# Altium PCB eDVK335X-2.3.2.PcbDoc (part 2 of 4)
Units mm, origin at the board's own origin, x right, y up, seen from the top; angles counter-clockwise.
Board outline 100.04 x 80.07 mm, 4 copper layers (Top Layer, Layer 1, Layer 2, Bottom Layer), stack 0.569 mm thick; 245 components, 272 nets, 1313 pads, 662 vias.
Unrouted connection lines stored in the file: 1.
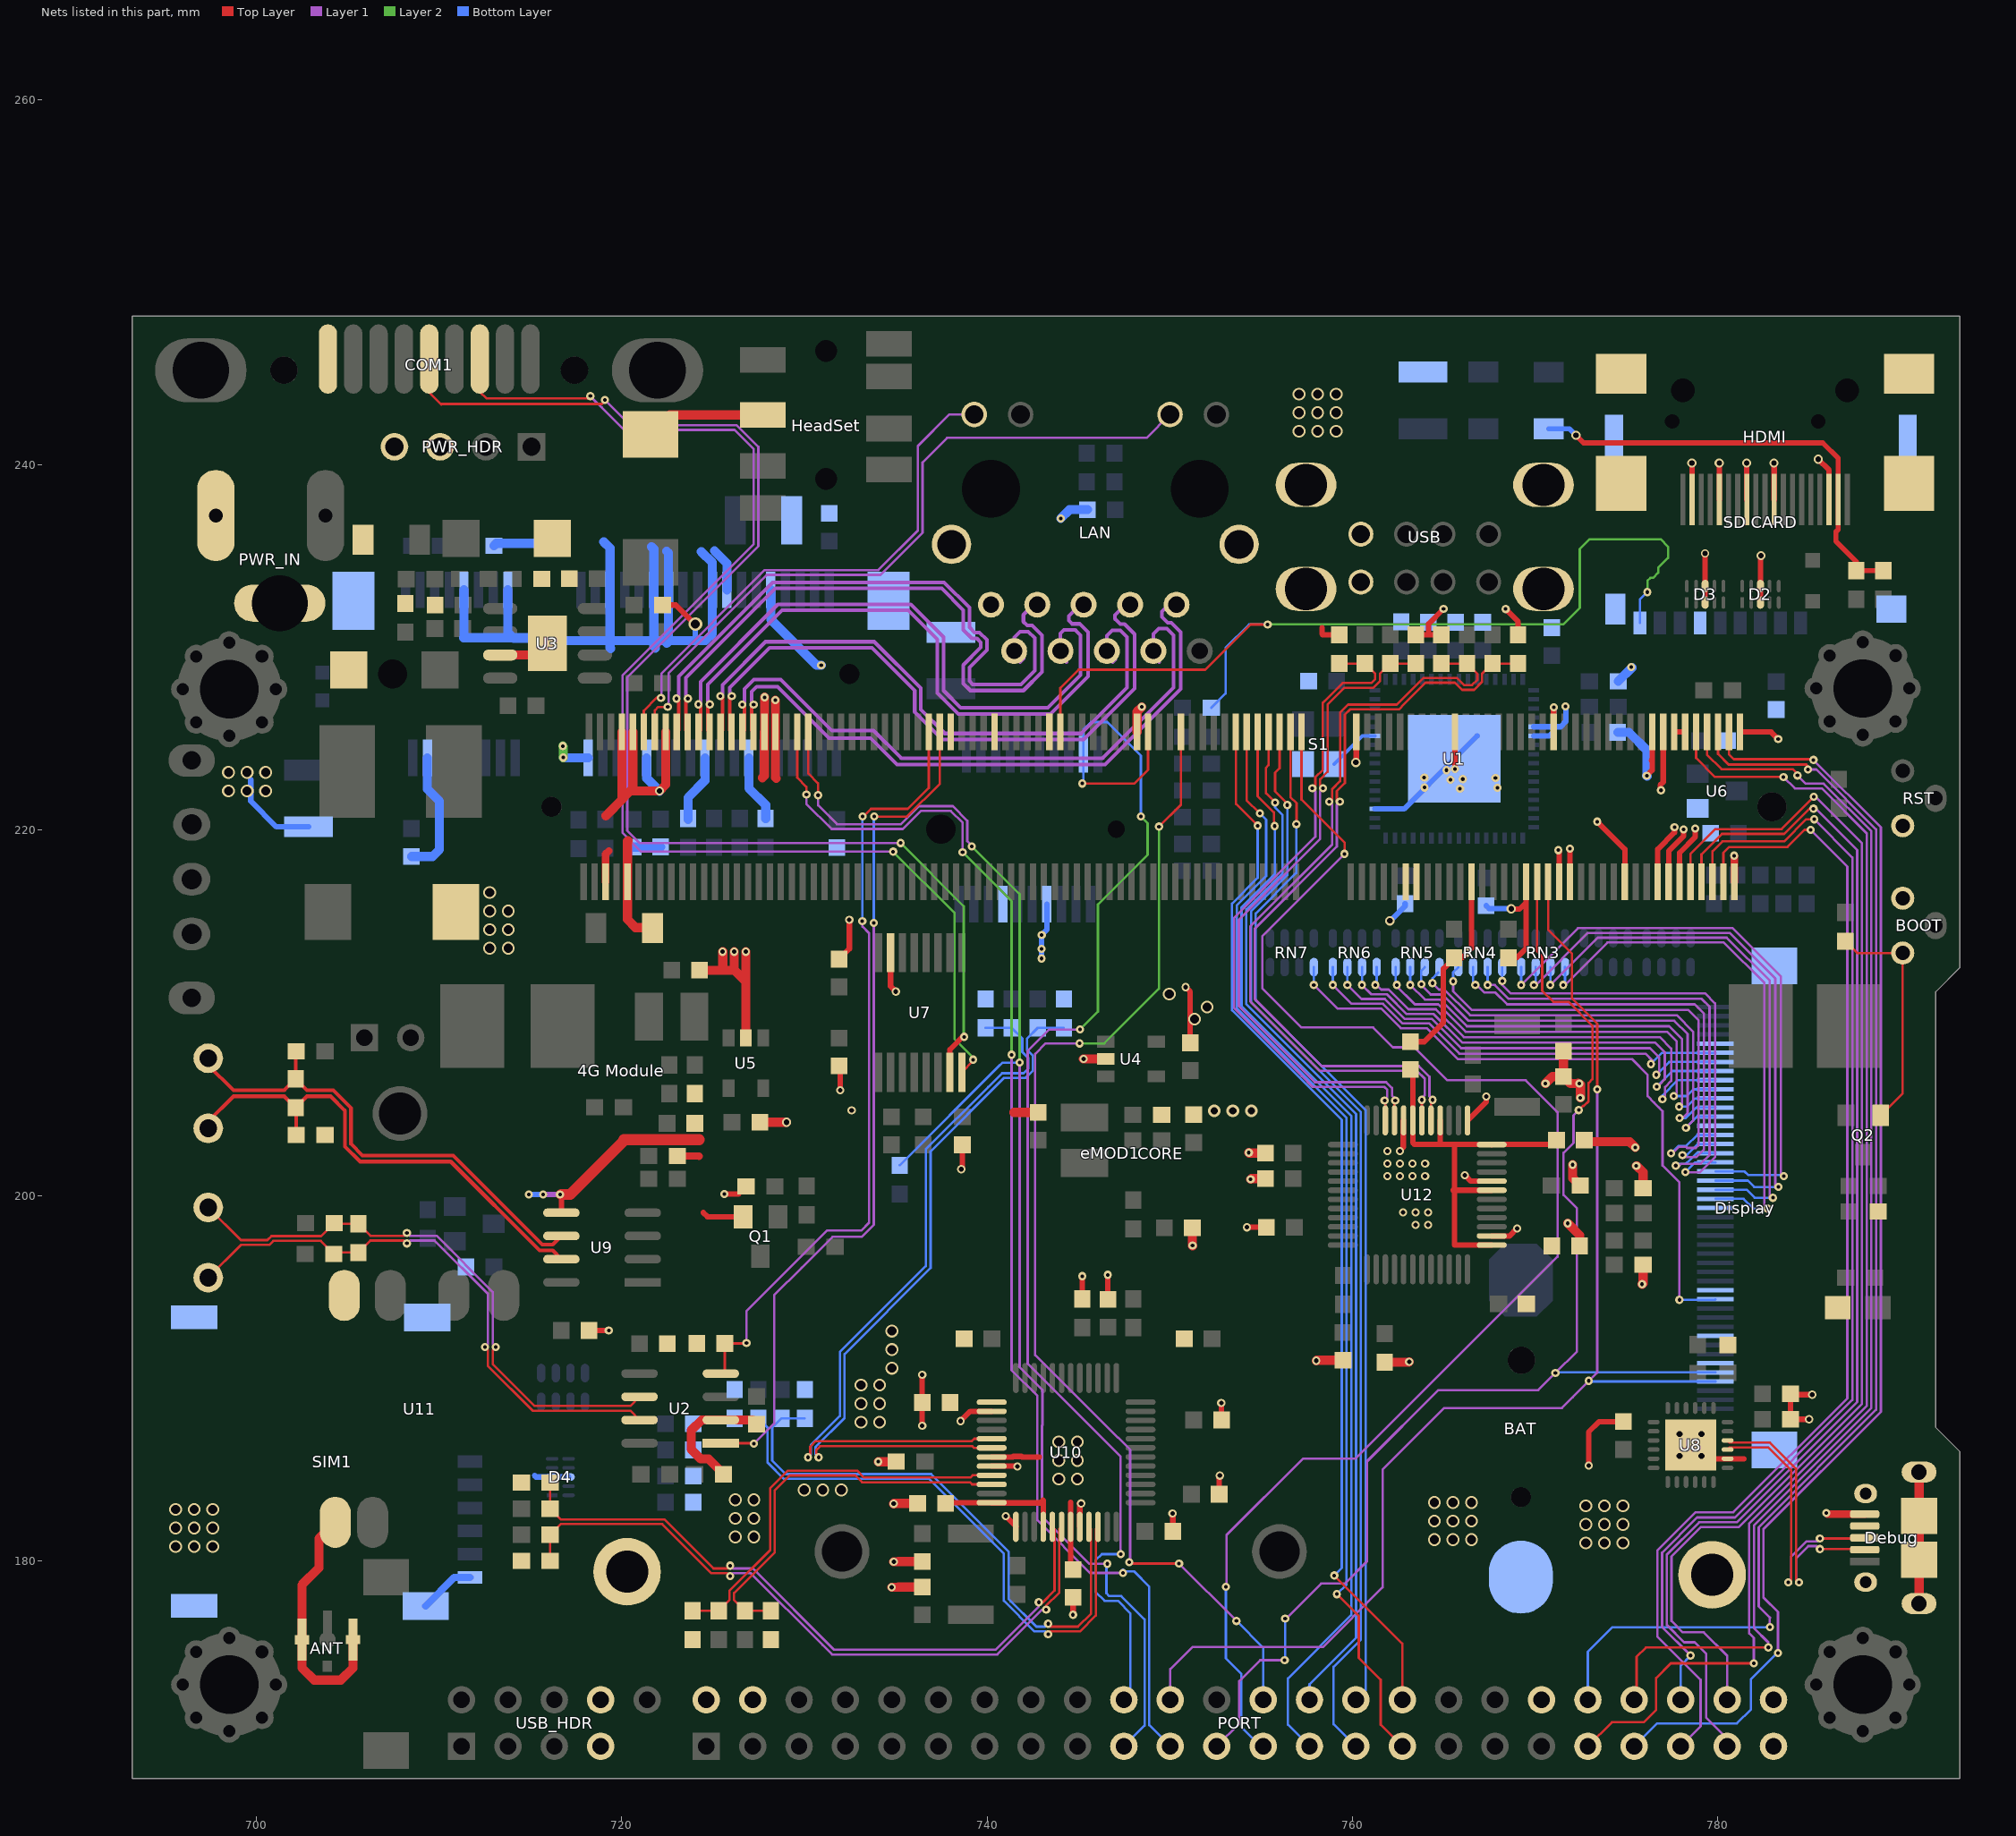
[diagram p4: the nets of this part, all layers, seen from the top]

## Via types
v1: diameter 0.45, hole 0.2, Top Layer to Bottom Layer, tented both sides, 424 vias
v2: diameter 0.7, hole 0.5, Top Layer to Bottom Layer, tented both sides, 146 vias
v3: diameter 0.45, hole 0.25, Top Layer to Bottom Layer, tented both sides, 55 vias
v4: diameter 0.5, hole 0.3, Top Layer to Bottom Layer, tented both sides, 17 vias
v5: diameter 0.7, hole 0.4, Top Layer to Bottom Layer, tented both sides, 13 vias
v6: diameter 0.66, hole 0.33, Top Layer to Bottom Layer, tented both sides, 4 vias
v7: diameter 0.75, hole 0.5, Top Layer to Bottom Layer, tented both sides, 1 vias
v8: diameter 0.5, hole 0.2, Top Layer to Bottom Layer, tented both sides, 1 vias
v9: diameter 0.45, hole 0.3, Top Layer to Bottom Layer, tented both sides, 1 vias

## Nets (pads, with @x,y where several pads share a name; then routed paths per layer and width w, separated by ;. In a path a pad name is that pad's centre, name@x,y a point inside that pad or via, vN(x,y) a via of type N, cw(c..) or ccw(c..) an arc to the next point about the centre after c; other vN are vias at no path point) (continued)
1D3_N: R94.2 R150.1 U12.17 | length 43
  Top Layer w0.13: v1(759.31,221.56) 759.19,221.56 759.15,221.6 759.15,222.142 759.59,222.582 759.59,226.34 759.87,226.62 762.54,226.62 762.84,226.92 ; 762.84,226.92 763.238,227.318 ; 763.238,227.318 764,228.08 765.612,228.08 766.002,227.69 766.658,227.69 767.095,228.127 767.095,228.559 R94.2@767.663,229.127 R150.1@769.06,229.127 ; U12.17@764.302,204.115 v1@764.302,205.168 ; v1@764.302,205.34 v1@764.302,205.24 ; v1(764.388,205.24) v1@764.302,205.24 ; v1@764.302,205.168 v1@764.302,205.24 ; v1@764.302,205.168 764.23,205.24 v1@764.302,205.24
  Layer 1 w0.13: v1(759.31,221.56) 759.15,221.4 759.15,219.11 754.66,214.62 754.66,210.75 758.32,207.09 763.638,207.09 764.22,206.508 764.22,205.422 v1@764.302,205.34
1D3_P: R95.2 R149.1 U12.18 | length 42.8
  Top Layer w0.13: v1(758.73,221.56) 758.85,221.56 758.89,221.6 758.89,222.25 759.33,222.69 759.33,226.448 759.762,226.88 762.432,226.88 762.732,227.18 ; 762.732,227.18 762.978,227.426 ; 762.978,227.426 763.892,228.34 765.72,228.34 766.11,227.95 766.55,227.95 766.835,228.235 766.835,228.559 R95.2@766.266,229.127 R149.1@764.869,229.127 ; U12.18@763.802,204.115 v1@763.802,205.246 ; v1@763.802,205.329 v1@763.802,205.246 ; v1(763.806,205.241) v1@763.802,205.246
  Layer 1 w0.13: v1(758.73,221.56) 758.89,221.4 758.89,219.218 754.4,214.728 754.4,210.642 757.702,207.34 758.212,206.83 763.53,206.83 763.96,206.4 763.96,205.488 v1@763.802,205.329
1D4_N: R51.2 R123.1 U12.21 | length 36.7
  Top Layer w0.13: v1(758.39,222.3) 758.38,222.3 758.23,222.45 758.23,222.792 758.64,223.202 758.64,226.87 759.57,227.8 761.144,227.8 761.507,228.162 761.507,228.559 R51.2@762.075,229.127 R123.1@763.472,229.127 ; U12.21@762.302,204.115 v1@762.302,205.34
  Layer 1 w0.13: v1(758.39,222.3) 758.23,222.14 758.23,219.54 753.78,215.09 753.78,210.37 757.94,206.21 761.85,206.21 762.17,205.89 762.17,205.471 v1@762.302,205.34
  other v1: 762.342,205.2
1D4_P: R52.2 R122.1 U12.22 | length 36.9
  Top Layer w0.13: v1(757.81,222.3) 757.82,222.3 757.97,222.45 757.97,222.9 758.38,223.31 758.38,226.978 758.456,227.054 759.462,228.06 761.037,228.06 761.247,228.27 761.247,228.559 R52.2@760.678,229.127 R122.1@759.281,229.127 ; v1@761.719,205.24 v1@761.802,205.24 ; U12.22@761.802,204.115 v1@761.802,205.24 ; v1@761.802,205.329 v1@761.802,205.24
  Layer 1 w0.13: v1(757.81,222.3) 757.97,222.14 757.97,219.648 753.52,215.198 753.52,210.262 757.232,206.55 757.832,205.95 761.742,205.95 761.91,205.782 761.91,205.351 v1(761.758,205.2)
2D1_N: R42.2 R125.1 U10.9 | length 22
  Top Layer w0.13: R125.1@723.882,177.271 R42.2@725.309,177.271 725.892,177.855 725.892,178.348 728.12,180.576 728.12,183.968 729.092,184.94 732.89,184.94 733.263,184.567 739.08,184.567 739.2,184.687 U10.9@740.251,184.687
2D1_P: R43.2 R124.1 U10.10 | length 21.6
  Top Layer w0.13: R124.1@728.162,177.271 R43.2@726.735,177.271 726.152,177.855 726.152,178.24 728.38,180.468 728.38,183.86 729.2,184.68 732.782,184.68 733.155,184.307 739.06,184.307 739.18,184.187 U10.10@740.251,184.187
2D2_N: R60.2 R119.1 U10.5 | length 41.7
  Top Layer w0.13: v1(730.195,185.67) 730.32,185.795 730.32,186.257 730.623,186.56 739.17,186.56 739.297,186.687 U10.5@740.251,186.687
  Bottom Layer w0.13: v1(730.195,185.67) 730.355,185.83 730.355,186.348 731.94,187.933 731.94,191.43 736.65,196.14 736.65,202.528 740.07,205.948 740.822,206.7 742,206.7 742.25,206.95 742.25,207.54 741.93,207.86 741.93,208.599 R60.2@741.347,209.183 R119.1@739.92,209.183
2D2_P: R61.2 R118.1 U10.6 | length 41.2
  Top Layer w0.13: v1(730.775,185.67) 730.65,185.795 730.65,186.07 730.86,186.28 739.19,186.28 739.283,186.187 U10.6@740.251,186.187
  Bottom Layer w0.13: v1(730.775,185.67) 730.615,185.83 730.615,186.24 732.2,187.825 732.2,191.322 736.91,196.032 736.91,202.42 740.93,206.44 742.108,206.44 742.51,206.842 742.51,207.648 742.19,207.968 742.19,208.599 R61.2@742.773,209.183 R118.1@744.2,209.183
2D3_N: R62.2 R152.1 U10.17 | length 37.6
  Top Layer w0.13: R152.1@716.081,184.283 R62.2@716.081,182.856 716.664,182.273 722.327,182.273 725.02,179.58 725.77,179.58 v1(725.93,179.74) ; v1(742.827,177.733) 742.85,177.71 743.03,177.71 743.696,178.375 743.696,181.742 U10.17@743.576,181.862
  Layer 1 w0.13: v1@725.95,179.58 725.93,179.6 v1(725.93,179.74) 726.09,179.58 727.18,179.58 731.63,175.13 740.45,175.13 742.827,177.507 v1(742.827,177.733)
2D3_P: R63.2 R151.1 U10.18 | length 38
  Top Layer w0.13: R151.1@716.081,180.021 R63.2@716.081,181.43 716.664,182.013 722.219,182.013 724.912,179.32 725.77,179.32 v1(725.93,179.16) ; v1(743.237,177.323) 743.214,177.346 743.214,177.526 743.955,178.268 743.955,181.742 U10.18@744.075,181.862
  Layer 1 w0.13: v1@725.95,179.32 725.93,179.3 v1(725.93,179.16) 726.09,179.32 727.072,179.32 730.997,175.395 731.522,174.87 740.558,174.87 743.011,177.323 v1(743.237,177.323)
2D4_N: R96.2 R148.1 U10.21 | length 31.8
  Top Layer w0.13: v1(743.34,176.56) 743.34,176.49 743.43,176.4 744.976,176.4 745.696,177.12 745.696,181.742 U10.21@745.576,181.862
  Bottom Layer w0.13: R148.1@730.02,187.803 R96.2@728.75,187.803 728.24,187.293 728.24,185.49 728.98,184.75 736.938,184.75 741.18,180.508 741.18,177.92 742.7,176.4 743.18,176.4 v1(743.34,176.56)
2D4_P: R97.2 R147.1 U10.22 | length 32.7
  Top Layer w0.13: v1(743.34,175.98) 743.34,176.05 743.43,176.14 745.083,176.14 745.956,177.012 745.956,181.742 U10.22@746.076,181.862
  Bottom Layer w0.13: R147.1@726.18,187.803 R97.2@727.47,187.803 727.98,187.293 727.98,185.382 728.872,184.49 736.83,184.49 740.92,180.4 740.92,177.812 742.592,176.14 743.18,176.14 v1(743.34,175.98)
12MHZ: S1.3 U1.27 | length 2.9
  Bottom Layer w0.2: S1.3@759.001,223.622 760.544,225.164 U1.27@761.225,225.164
AB_N: R101.2 R103.2 RS485.2 U9.7 | length 27.1
  Top Layer w0.2: RS485.2@697.363,203.678 697.363,204.058 698.74,205.435 701.528,205.435 R101.2@702.15,204.813 ; R103.2@702.183,203.32 702.183,204.78 R101.2@702.15,204.813 ; U9.7@716.695,196.519 716.225,196.989 715.511,196.989 710.64,201.86 705.673,201.86 704.85,202.683 704.85,204.65 704.065,205.435 702.772,205.435 R101.2@702.15,204.813
AB_P: R99.2 R101.1 RS485.1 U9.6 | length 27.2
  Top Layer w0.2: RS485.1@697.363,207.518 697.363,207.142 698.74,205.765 701.528,205.765 R101.1@702.15,206.387 ; R99.2@702.183,207.89 702.15,207.857 R101.1@702.15,206.387 ; U9.6@716.695,197.789 716.225,197.319 715.648,197.319 710.777,202.19 705.81,202.19 705.18,202.82 705.18,204.787 704.202,205.765 702.772,205.765 R101.1@702.15,206.387
AIN0: CORE.9 PORT.39 | length 72.7
  Top Layer w0.13: PORT.39@772.89,169.85 774.21,171.17 775.96,171.17 776.63,171.84 776.63,173.59 777.43,174.39 v1(781.97,174.39) ; CORE.9@778.811,225.38 778.811,223.959 779.85,222.92 783.4,222.92 783.41,222.91 v1(783.6,222.91)
  Layer 1 w0.13: v1(781.97,174.39) 781.97,175.78 781.72,176.03 781.72,182.053 788.15,188.483 788.15,219.837 785.697,222.29 784.22,222.29 v1(783.6,222.91)
AIN1: CORE.5 PORT.40 | length 71.6
  Top Layer w0.13: CORE.5@780.011,225.38 780.011,224.179 780.59,223.6 784.85,223.6 785.01,223.44 785.013,223.443 785.053,223.443 v1(784.938,223.33)
  Layer 1 w0.13: v1(782.85,176.37) 782.85,176.88 782.86,176.89 782.24,177.51 782.24,181.838 788.67,188.268 788.67,220.052 785.393,223.33 v1(784.938,223.33)
  Bottom Layer w0.13: PORT.40@772.89,172.39 772.89,175.02 774.235,176.365 ; 774.23,176.37 v1(782.85,176.37)
AIN2: CORE.3 PORT.41 | length 71.6
  Top Layer w0.13: CORE.3@780.611,225.38 780.611,224.149 780.87,223.89 785.2,223.89 v1(785.24,223.85)
  Layer 1 w0.13: 782.5,179.11 782.5,177.99 ; v1(783.3,174.96) 783.3,177.17 783.31,177.18 782.5,177.99 ; v1(785.24,223.85) 788.93,220.16 788.93,188.16 782.5,181.73 782.5,177.99
  Bottom Layer w0.13: PORT.41@775.43,169.85 776.68,171.1 781.04,171.1 781.82,171.88 781.82,173.53 783.31,175.02 783.3,175.01 v1(783.3,174.96)
AIN3: CORE.7 PORT.42 | length 69.6
  Top Layer w0.13: PORT.42@775.43,172.39 775.56,172.52 775.56,174.76 776.06,175.26 v1(782.77,175.26) ; CORE.7@779.411,225.38 779.411,224.129 780.2,223.34 784.1,223.34 784.42,223.02 784.38,223.02 v1(784.36,223)
  Layer 1 w0.13: v1(782.77,175.26) 782.77,175.53 781.98,176.32 781.98,181.945 788.41,188.375 788.41,219.945 785.805,222.55 784.81,222.55 v1(784.36,223)
AIN4: CORE.4 PORT.43 | length 64.8
  Top Layer w0.13: CORE.4@780.311,217.18 780.311,218.771 780.62,219.08 783.81,219.08 784.75,220.02 v1(785.078,220.02)
  Layer 1 w0.13: PORT.43@777.97,169.85 779.06,170.94 779.06,173.495 776.69,175.865 776.69,180.56 778.79,182.66 780.856,182.66 787.09,188.894 787.09,218.008 v1(785.078,220.02)
AIN5: CORE.6 PORT.44 | length 63.5
  Top Layer w0.13: CORE.6@779.711,217.18 779.711,218.851 780.25,219.39 783.63,219.39 784.84,220.6 v1(785.278,220.6)
  Layer 1 w0.13: v1@778.51,174.84 v1(778.51,174.82) 776.95,176.38 776.95,180.452 778.874,182.376 780.94,182.376 787.37,188.806 787.37,218.508 v1(785.278,220.6)
  Bottom Layer w0.13: PORT.44@777.97,172.39 777.97,174.28 v1(778.51,174.82)
AIN6: CORE.8 PORT.45 | length 68.3
  Top Layer w0.13: CORE.8@779.111,217.18 779.111,218.684 780.228,219.8 783.64,219.8 785.02,221.18 v1(785.24,221.18)
  Layer 1 w0.13: PORT.45@780.51,169.85 780.51,170.27 779.37,171.41 779.37,174.9 778.73,175.54 778.158,175.54 777.21,176.488 777.21,180.345 778.982,182.116 781.048,182.116 787.63,188.698 787.63,218.92 785.37,221.18 v1(785.24,221.18)
AIN7: CORE.10 PORT.46 | length 67.6
  Top Layer w0.13: CORE.10@778.511,217.18 778.511,218.711 779.86,220.06 783.49,220.06 v1(785.26,221.83)
  Layer 1 w0.13: PORT.46@780.51,172.39 780.51,174.82 779.24,176.09 778.09,176.09 777.47,176.71 777.47,180.237 779.089,181.856 781.155,181.856 787.89,188.591 787.89,219.29 785.35,221.83 v1(785.26,221.83)
AVDD33: C76.1 C77.1 C78.1 L7.2 U10.1 U10.7 U10.12 U10.16 U10.19 | length 13.5
  Top Layer w0.3: C77.1@737.722,183.143 737.766,183.187 U10.12@740.251,183.187 740.251,183.169 742.865,183.169 ; U10.7@740.251,185.687 741.4,185.687 741.433,185.72 741.884,185.72 741.917,185.687 742.861,185.687 742.865,185.683 ; 743.056,183.333 743.076,183.313 743.076,183.206 ; U10.16@743.076,181.862 743.076,183.143 ; 744.58,183.206 744.576,183.202 U10.19@744.576,181.862 744.576,179.654 C76.1@744.707,179.523 ; 742.865,183.169 743.049,183.169 743.076,183.143 ; 742.865,183.169 742.902,183.206 743.076,183.206 ; 743.076,183.143 743.076,183.206
AVDD33_2: C93.1 C94.1 C95.1 L6.2 U12.1 U12.7 U12.12 U12.16 U12.19 | length 23.1
  Top Layer w0.3: C94.1@763.171,206.898 763.302,206.767 U12.19@763.302,204.115 763.302,202.894 763.388,202.808 764.822,202.808 ; U12.16@764.802,204.115 764.802,202.828 764.822,202.808 ; 765.52,200.294 765.524,200.29 765.584,200.29 ; U12.1@767.627,197.29 765.603,197.29 765.584,197.31 765.584,200.29 ; U12.7@767.627,200.29 765.584,200.29 ; U12.12@767.627,202.79 U12.12@767.609,202.808 ; C95.1@771.17,203.034 770.943,202.808 U12.12@767.609,202.808 ; 764.822,202.808 765.584,202.808 ; 765.584,200.29 765.584,202.808 ; 765.584,202.808 U12.12@767.609,202.808
B0: Display.40 RN6.8 | length 24.4
  Layer 1 w0.13: v1(758.924,211.53) 759.954,210.5 761.668,210.5 762.748,209.42 764.21,209.42 765.86,207.77 776.05,207.77 776.45,207.37 776.45,207.24 776.49,207.2 v1(776.338,207.2)
  Bottom Layer w0.13: v1@758.927,211.533 RN6.8@758.927,212.509 ; v1(776.338,207.2) 776.957,207.819 Display.40@779.871,207.819
B1: Display.39 RN6.7 | length 24.4
  Layer 1 w0.13: v1(759.724,211.53) 760.494,210.76 761.776,210.76 762.856,209.68 764.34,209.68 765.95,208.07 776.28,208.07 776.8,207.55 776.8,206.6 776.79,206.59 776.658,206.59 v1(776.638,206.61)
  Bottom Layer w0.13: v1@759.727,211.533 RN6.7@759.727,212.509 ; v1(776.638,206.61) 777.347,207.319 Display.39@779.871,207.319
B2: Display.38 RN6.6 | length 24.8
  Layer 1 w0.13: v1(760.524,211.53) 761.034,211.02 761.884,211.02 762.964,209.94 764.45,209.94 766.02,208.37 776.58,208.37 777.1,207.85 777.1,206.37 776.82,206.09 776.82,205.97 v1(776.658,205.97)
  Bottom Layer w0.13: v1@760.527,211.533 RN6.6@760.527,212.509 ; v1(776.658,205.97) 777.507,206.819 Display.38@779.871,206.819
B3: Display.37 RN6.5 | length 25.1
  Layer 1 w0.13: v1@761.324,211.53 761.574,211.28 761.992,211.28 763.072,210.2 764.57,210.2 766.1,208.67 776.83,208.67 777.45,208.05 777.45,206.27 777.12,205.94 v1@777.12,205.28 ; v1(776.968,205.28) v1@777.12,205.28
  Bottom Layer w0.13: v1@761.327,211.533 RN6.5@761.327,212.509 ; v1(776.968,205.28) 776.968,205.48 777.807,206.319 Display.37@779.871,206.319
  other v1: 761.254,211.53
B4: Display.36 RN5.8 | length 23.4
  Layer 1 w0.13: v1@762.361,211.53 763.421,210.47 764.7,210.47 766.2,208.97 777.216,208.97 777.75,208.436 777.75,205.382 777.703,205.335 v1(777.588,205.45)
  Bottom Layer w0.13: v1@762.364,211.533 RN5.8@762.364,212.509 ; v1(777.588,205.45) 778.31,205.45 778.679,205.819 Display.36@779.871,205.819
  other v1: 762.431,211.53
B5: Display.35 RN5.7 | length 23.1
  Layer 1 w0.13: v1(763.161,211.53) 763.961,210.73 764.81,210.73 766.27,209.27 777.34,209.27 778.05,208.56 778.05,204.91 777.949,204.809 v1(777.888,204.87)
  Bottom Layer w0.13: v1@763.164,211.533 RN5.7@763.164,212.509 ; v1(777.888,204.87) 778.31,204.87 778.759,205.319 Display.35@779.871,205.319
B6: Display.34 RN5.6 | length 23.8
  Layer 1 w0.13: v1@763.8,211.45 763.841,211.45 764.281,211.01 764.92,211.01 766.36,209.57 777.626,209.57 778.35,208.846 778.35,204.52 778.01,204.18 777.96,204.18 777.97,204.19 777.91,204.25 v1(777.908,204.25)
  Bottom Layer w0.13: v1(763.77,211.57) 763.77,212.314 RN5.6@763.964,212.509 ; v1(777.908,204.25) 778.25,204.25 778.819,204.819 Display.34@779.871,204.819
B7: Display.33 RN5.5 | length 23.4
  Layer 1 w0.13: v1(764.38,211.63) 764.73,211.28 765.03,211.28 766.44,209.87 777.75,209.87 778.65,208.97 778.65,204.1 v1(778.26,203.71)
  Bottom Layer w0.13: v1(764.38,211.63) 764.38,211.894 RN5.5@764.695,212.209 ; v1(778.26,203.71) 778.869,204.319 Display.33@779.871,204.319
BOOT_SEL: BOOT.2 Q2.1 R1.1 | length 12.8
  Top Layer w0.13: R1.1@786.98,213.923 787.623,213.28 BOOT.2@790.12,213.28 790.12,205.587 Q2.1@788.922,204.389
CAN0_RX: C34.1 CORE.141 U2.4 | length 43.8
  Top Layer w0.13: U2.4@725.427,190.252 725.642,190.467 C34.1@725.642,191.9 726.8,191.9 v1(726.83,191.93) ; v1(733.18,220.76) 733.236,220.76 733.646,221.17 735.662,221.17 736.811,222.319 CORE.141@736.811,225.38
  Layer 1 w0.13: v1(726.83,191.93) 726.83,193.68 731.23,198.08 ; 731.93,198.08 731.23,198.08 ; v1(733.17,215.03) 733.18,215.02 733.18,214.72 733.54,214.36 733.54,198.508 733.112,198.08 731.23,198.08
  Bottom Layer w0.13: v1(733.17,215.03) 733.17,220.75 v1(733.18,220.76)
CAN0_TX: CORE.139 U2.1 | length 47
  Top Layer w0.13: U2.1@725.427,186.442 727.208,186.442 v1(727.24,186.41) ; v1(733.82,220.75) 735.61,220.75 737.411,222.551 CORE.139@737.411,225.38
  Layer 1 w0.13: v1(727.24,186.41) 728.34,187.51 728.34,194.54 729.85,196.05 731.54,197.74 733.14,197.74 733.8,198.4 v1(733.8,214.92)
  Bottom Layer w0.13: v1(733.8,214.92) 733.8,220.72 733.82,220.74 v1(733.82,220.75)
CAN_N: CAN.1 R68.2 R69.1 U2.6 | length 32.2
  Top Layer w0.13: CAN.1@697.363,199.348 699.153,197.558 700.598,197.558 700.82,197.78 703.547,197.78 R69.1@704.267,198.5 704.31,198.457 R68.2@705.58,198.457 706.237,197.8 708.08,197.8 v1(708.24,197.96) ; v1(713.1,191.7) 712.94,191.54 712.94,190.77 715.23,188.48 720.471,188.48 U2.6@720.973,188.982
  Top Layer w0.3: CAN.1@697.363,198.787 CAN.1@697.363,199.348
  Layer 1 w0.13: v1(708.24,197.96) 708.4,197.8 709.858,197.8 712.94,194.718 712.94,191.86 v1(713.1,191.7)
CAN_P: CAN.2 R67.2 R68.1 U2.7 | length 32.3
  Top Layer w0.13: CAN.2@697.363,195.508 699.153,197.298 700.706,197.298 700.928,197.52 703.53,197.52 R67.2@704.24,196.81 704.313,196.883 R68.1@705.58,196.883 706.237,197.54 708.08,197.54 v1(708.24,197.38) ; v1(712.52,191.7) 712.68,191.54 712.68,190.662 715.122,188.22 720.465,188.22 U2.7@720.973,187.712
  Top Layer w0.3: CAN.2@697.363,195.508 CAN.2@697.363,196.143
  Layer 1 w0.13: v1(708.24,197.38) 708.4,197.54 709.75,197.54 712.68,194.61 712.68,191.86 v1(712.52,191.7)
COM1_RX: COM1.2 U7.8 | length 71.6
  Top Layer w0.13: COM1.2@712.23,245.8 712.23,244.01 712.6,243.64 718.15,243.64 v1(718.28,243.77) ; U7.8@738.615,206.749 739.24,207.374 v1(739.24,207.44)
  Layer 1 w0.13: v1(718.28,243.77) 718.28,243.766 718.906,243.14 718.91,243.14 720.13,241.92 726.182,241.92 727.22,240.882 727.22,235.654 720.04,228.474 720.04,219.862 721.072,218.83 v1(734.86,218.83)
  Layer 2 w0.13: v1(734.86,218.83) 738.21,215.48 738.21,208.59 739.24,207.56 v1(739.24,207.44)
COM1_TX: COM1.3 U7.7 | length 75
  Top Layer w0.13: COM1.3@709.46,245.8 709.46,243.965 710.12,243.305 710.155,243.34 718.93,243.34 719.08,243.49 v1(719.08,243.56)
  Top Layer w0.3: U7.7@737.965,206.749 737.965,207.995 v1@738.74,208.77
  Layer 1 w0.13: v1(719.08,243.56) 720.46,242.18 726.29,242.18 727.48,240.99 727.48,235.546 720.3,228.366 720.3,219.97 720.97,219.3 v1(735.26,219.3)
  Layer 2 w0.13: v1(735.26,219.3) 738.72,215.84 738.72,208.68 738.73,208.68 v1(738.74,208.69)
DE: Display.13 RN7.1 | length 36.3
  Layer 1 w0.13: v1(757.887,211.53) 759.177,210.24 761.561,210.24 762.641,209.16 764.08,209.16 765.77,207.47 775.3,207.47 776.16,206.61 776.16,205.44 776.508,205.092 776.508,205.089 776.778,204.82 776.78,204.82 776.98,204.62 776.98,201.64 777.9,200.72 v1(777.9,194.29)
  Bottom Layer w0.13: v1@757.89,211.533 RN7.1@757.89,212.509 ; v1(777.9,194.29) 779.843,194.29 Display.13@779.871,194.319
DGND: "4G Module.4" "4G Module.9" "4G Module.15" "4G Module.18" "4G Module.21" "4G Module.26" "4G Module.27" "4G Module.29" "4G Module.34" "4G Module.35" "4G Module.37" "4G Module.40" "4G Module.43" "4G Module.M1" "4G Module.M2" "SD CARD.6" "SD CARD.10" "SD CARD.11" "SD CARD.12" "SD CARD.13" ANT.2 BAT.2 BOOT.1 C1.2 C2.2 C3.2 C4.2 C5.2 C6.2 C7.2 C8.2 C13.1 C14.2 C15.1 C16.1 C17.1 C18.1 C19.1 C20.1 C21.1 C22.1 C23.1 C24.2 C25.2 C33.2 C34.2 C35.2 C37.2 C38.2 C39.2 C40.2 C41.2 C42.2 C44.2 C45.2 C46.2 C47.2 C48.2 C49.2 C50.2 C51.2 C59.2 C60.2 C62.1 C64.1 C65.1 C66.1 C67.1 C68.1 C69.2 C70.2 C71.2 C72.2 C73.2 C74.2 C75.2 C76.2 C77.2 C78.2 C89.2 C90.2 C91.2 C92.2 C93.2 C94.2 C95.2 C96.2 C97.2 CC1.1 CC2.1 CC3.1 COM1.5 CORE.1 CORE.2 CORE.11 CORE.12 CORE.13 CORE.14 CORE.15 CORE.16 CORE.17 CORE.22 CORE.32 CORE.34 CORE.35 CORE.40 CORE.50 CORE.53 CORE.60 CORE.62 CORE.71 CORE.103 CORE.119 CORE.129 CORE.137 CORE.169 CORE.171 CORE.189 CORE.195 CORE.196 CORE.197 CORE.200 Cp1.2 D2.3 D2.8 D3.3 D3.8 D4.3 D4.8 D6.1 D7.2 D8.1 Debug.4 Debug.5 Debug.G1 Debug.G2 Debug.G3 Debug.G4 Debug.G5 Debug.G6 Display.6 Display.9 Display.14 Display.23 Display.32 Display.41 Display.A Display.B eMOD1.7 eMOD1.13 HDMI.2 HDMI.5 HDMI.8 HDMI.11 HDMI.17 HDMI.20 HDMI.21 HDMI.22 HDMI.23 HeadSet.2 LAN.10 LAN.S1 LAN.S2 PORT.2 PORT.4 PORT.38 PORT.47 PORT.48 PWR_HDR.3 PWR_HDR.4 PWR_IN.2 PWR_IN.3 Q1.E R3.1 R6.2 R20.2 R37.2 R39.2 R40.2 R55.2 R66.1 R74.2 R75.2 R78.2 R81.2 R102.2 R103.1 R107.2 R118.2 R119.2 R120.2 R121.2 R122.2 R123.2 R124.2 R125.2 R130.2 R133.2 R135.2 R145.2 R146.2 R147.2 R148.2 R149.2 R150.2 R151.2 R152.2 R153.2 RST.2 S1.2 SIM1.4 SIM1.G1 SIM1.G2 SIM1.G3 SIM1.G4 U1.19 U1.53 U1.54 U1.65 U2.2 U3.7 U3.9 U4.2 U5.2 U6.1 U7.15 U8.2 U8.25 U9.5 U10.2 U10.8 U10.13 U10.20 U11.4 U11.5 U12.2 U12.8 U12.13 U12.20 USB.D4 USB.G1 USB.G2 USB.G3 USB.G4 USB.U4 USB_HDR.7 USB_HDR.8 | length 350
  Top Layer w0.3: U9.5@716.695,199.1 v1@716.695,200.06 ; C59.2@718.21,192.61 719.278,192.61 v1(719.288,192.62) ; R6.2@722.237,232.33 722.96,232.33 724.03,231.26 v7(724.03,231.29) ; 724.46,199.07 724.687,198.843 Q1.E@726.651,198.843 ; v1(725.62,200.09) 726.399,200.09 R102.2@726.803,200.494 ; C64.1@731.895,207.103 731.958,207.04 v3(731.958,205.77) ; C62.1@731.895,212.945 732.46,213.51 v3(732.46,215.09) ; v3(732.585,204.657) v3@732.619,204.622 ; U7.15@734.715,213.299 734.715,211.458 v3(735.006,211.167) ; v3(736.452,187.397) C78.2@736.452,188.667 v3(736.452,190.191) ; v3(738.547,187.651) 739.083,188.187 U10.2@740.251,188.187 ; v3(738.586,201.445) 738.65,201.508 C66.1@738.65,202.778 ; U10.8@740.251,185.187 741.646,185.187 v3(741.659,185.175) ; v3(741.024,182.444) 741.575,181.893 U10.13@741.575,181.862 ; v1(744.707,177.047) C76.2@744.707,177.999 ; U10.20@745.075,181.862 745.075,183.117 745.05,183.143 v3(745.151,183.143) ; R135.2@745.215,194.344 v1(745.215,195.585) ; C73.2@746.612,194.319 v1(746.612,195.658) ; v3(750.15,182.6) 750.168,182.582 C75.2@750.168,181.619 ; v3(750.865,211.412) 751.119,211.158 C48.2@751.119,208.364 ; C70.2@752.708,183.651 752.708,184.637 v3(752.74,184.67) ; v3(752.82,188.65) 752.835,188.635 C74.2@752.835,187.715 ; v3(754.217,198.262) C92.2@755.297,198.262 ; 758.33,231.09 758.33,230.75 758.378,230.702 R122.2@759.281,230.702 ; v4(760.19,223.71) 760.211,223.731 CORE.71@760.211,225.38 ; v3@762.58,202.44 762.787,202.647 762.787,204.101 U12.20@762.802,204.115 ; C94.2@763.171,208.422 763.933,208.422 764.98,209.47 764.98,212.423 R153.2@765.57,213.013 765.993,213.013 766.395,213.415 766.511,213.531 CORE.50@766.511,217.18 ; R123.2@763.472,230.702 764.171,230.702 ; R149.2@764.869,230.702 764.171,230.702 ; v1(764.99,232.12) 764.171,231.301 764.171,230.702 ; CORE.53@765.611,225.38 v1(765.611,223.359) v1@765.62,223.35 ; v3(766.155,201.12) 766.485,200.79 U12.8@767.627,200.79 ; v1(766.278,213.3) v1@766.394,213.415 ; U12.13@766.302,204.115 767.328,205.142 v3(767.328,205.42) ; U12.2@767.627,197.79 768.604,197.79 v3(769.013,198.199) ; v1(768.39,232.11) 769.06,231.44 R150.2@769.06,230.702 ; R40.2@768.54,213.013 768.973,213.013 769.511,213.551 769.511,216.051 ; v4(768.69,215.7) 768.71,215.68 769.14,215.68 769.511,216.051 ; CORE.40@769.511,217.18 769.511,216.051 ; CORE.35@771.011,225.38 771.011,226.711 v1(771.03,226.73) ; v1(771.27,218.91) 771.311,218.869 CORE.34@771.311,217.18 ; v1(771.91,218.99) CORE.32@771.911,217.18 CORE.32@771.911,217.18 ; v3(772.931,185.213) 772.931,187.054 773.503,187.626 C65.1@774.836,187.626 ; v1(773.4,220.47) 774.911,218.959 CORE.22@774.911,217.18 ; v1(776.11,222.98) 776.411,223.281 776.411,223.871 ; 776.36,223.82 776.411,223.871 ; CORE.17@776.411,225.38 776.411,223.871 ; CORE.16@776.711,217.18 776.711,218.961 777.63,219.88 v1(777.63,220.16) ; v1(776.89,222.19) 776.85,222.23 776.85,222.475 777.011,222.636 CORE.15@777.011,225.38 ; CORE.14@777.311,217.18 777.311,218.861 778.13,219.68 v1(778.13,220.04) ; CORE.13@777.611,225.38 CORE.11@778.211,225.38 ; CORE.12@777.911,217.18 777.911,218.771 778.77,219.63 v1(778.77,220.09) ; v4(778.58,240.1) 778.59,240.09 HDMI.2@778.59,238.099 ; v6(779.112,185.744) 779.262,185.594 U8.2@780.537,185.594 781.44,185.594 ; v9(779.3,235.16) 779.31,235.15 D3.8@779.31,233.368 D3.3@779.31,232.468 ; HDMI.5@780.09,238.099 v4@780.09,240.09 ; CORE.1@781.211,225.38 782.92,225.38 v1(783.31,224.99) ; HDMI.8@781.59,238.099 v4@781.59,240.09 ; D2.3@782.335,232.468 D2.8@782.335,233.368 782.335,235.015 v4(782.36,235.04) ; HDMI.11@783.09,238.099 v4@783.09,240.09 ; v3(784.996,187.753) C67.1@783.98,187.753 C68.1@783.98,189.15 784.03,189.1 v3(785.17,189.1) ; v4(785.5,240.31) 786.09,239.72 HDMI.17@786.09,238.099
  Top Layer w0.4: v1(716.62,200.06) v1@716.695,200.06 ; CORE.200@719.111,217.18 719.111,218.691 719.29,218.87 ; R20.2@723.047,202.17 724.21,202.17 724.23,202.15 ; v1(780.89,218.61) 780.911,218.589 CORE.2@780.911,217.18 ; v1(785.94,182.62) 786,182.56 Debug.5@788.045,182.56
  Top Layer w0.5: U11.5@704.315,182.11 703.42,181.215 703.42,179.61 702.493,178.683 ANT.2@702.493,175.681 702.493,174.147 703.17,173.47 704.62,173.47 705.287,174.137 ANT.2@705.287,175.694 ; U3.7@713.349,229.595 U3.9@715.305,229.595 ; 719.131,220.791 720.105,221.765 ; CORE.197@720.011,225.38 720.011,221.839 720.085,221.765 720.47,222.15 ; 720.35,219.43 720.311,219.391 CORE.196@720.311,217.18 720.311,215.119 720.76,214.67 721.669,214.67 C37.2@721.689,214.65 ; CORE.195@720.611,225.38 720.611,222.291 720.47,222.15 ; C41.2@721.571,241.665 722.646,242.74 HeadSet.2@727.73,242.74 ; CORE.189@722.411,225.38 722.411,222.491 v4(722.07,222.15) 720.47,222.15 ; C50.2@724.256,212.334 725.526,212.334 ; v3(725.526,213.35) 725.526,212.334 ; R66.1@725.567,184.74 725.567,184.773 724.76,185.58 724.33,185.58 723.8,186.11 723.8,187.14 724.372,187.712 U2.2@725.427,187.712 727.146,187.712 C35.2@727.38,187.478 ; v3(726.161,213.35) 726.161,212.334 ; U5.2@726.796,208.629 726.796,211.699 ; v3(726.796,213.35) 726.796,211.699 ; C51.2@727.558,204.016 v4(729.019,204.016) ; 727.7,222.87 727.811,222.981 CORE.171@727.811,225.38 727.826,225.395 727.826,227.271 727.82,227.277 v1(727.82,227.28) ; v1(728.41,227.12) v1(728.41,227.12) CORE.169@728.411,225.38 728.411,222.889 728.46,222.84 ; v1(734.039,185.429) R107.2@735.029,185.429 ; v3(734.77,178.56) 735.15,178.56 735.161,178.571 C72.2@736.452,178.571 ; v3(734.889,183.126) 734.907,183.143 C77.2@736.198,183.143 ; v3(734.89,179.95) 735.143,179.95 735.161,179.968 C71.2@736.452,179.968 ; 741.467,204.554 C47.2@742.801,204.554 ; v3(745.277,207.475) U4.2@746.506,207.475 ; CORE.103@748.211,225.38 748.211,226.492 v1(748.474,226.755) ; C39.2@751.232,198.23 751.232,197.278 v1(751.25,197.26) ; v1(754.33,202.35) 754.354,202.326 C91.2@755.233,202.326 ; v1(754.43,200.89) 754.469,200.929 C89.2@755.233,200.929 ; v3(758.027,190.96) 758.049,190.982 C90.2@759.488,190.982 ; R130.2@761.774,190.871 763.082,190.871 v3(763.107,190.896) ; v1(770.57,206.14) 770.948,206.517 C96.2@771.553,206.517 ; C97.2@771.553,207.914 C96.2@771.553,206.517 ; v1(771.79,198.48) 772.442,197.828 C93.2@772.442,197.246 ; v1(772.06,201.69) 772.06,200.955 R133.2@772.467,200.548 ; v1@772.35,206.16 v1@772.38,206.13 ; v1(772.42,206.13) v1@772.38,206.13 ; v1(772.48,205.35) v1@772.48,206.07 ; C95.2@772.694,203.034 772.694,202.945 775.175,202.945 v1(775.49,202.63) ; v1(775.54,201.62) 775.57,201.62 775.909,201.281 R145.2@775.909,200.403 ; v1(775.86,195.15) 775.909,195.199 R146.2@775.909,196.212 ; Debug.G1@791.02,177.66 Debug.G2@791.02,180.06 Debug.G3@791.02,182.46 Debug.G4@791.02,184.86 ; 725.526,212.334 726.161,212.334 ; 726.161,212.334 726.796,211.699 ; C96.2@771.553,206.517 771.94,206.13 v1@772.38,206.13
  Top Layer w0.6: v1@716.695,200.06 717.18,200.06 720.12,203 ; 720.12,203.06 724.24,203.06
  Layer 1 w0.3: v1(715.7,200.06) v1(716.62,200.06)
  Layer 2 w0.5: v1(716.77,224.61) 716.8,224.58 v1(716.8,223.98)
  Bottom Layer w0.3: 699.69,222.76 699.69,221.6 701.099,220.191 CC2.1@702.85,220.191 ; v1(714.91,200.06) v1(715.7,200.06) ; 715.23,184.67 715.31,184.59 D4.3@716.19,184.59 D4.8@717.09,184.59 ; v7(724.03,231.29) 724.03,230.46 724.11,230.38 ; v1(742.979,212.98) 742.979,212.941 742.98,212.94 v1(742.98,213.51) 742.99,213.52 v1(742.99,214.26) 742.99,214.27 743.27,214.55 eMOD1.7@743.27,215.96 ; U1.19@761.225,221.164 762.825,221.164 U1.65@765.575,223.914 U1.65@766.825,225.164 ; v4(762.048,215.04) 762.05,215.04 762.07,215.02 762.07,215.04 762.88,215.85 C1.2@762.88,215.978 ; C3.2@767.32,215.868 767.478,215.71 768.69,215.71 v4(768.69,215.7) ; U1.54@769.925,225.164 770.764,225.164 771.03,225.43 771.03,225.665 ; U1.53@769.925,225.665 771.03,225.665 ; v1(771.03,226.73) 771.03,225.665 ; v1(771.658,226.78) v1(771.658,226.78) 771.66,226.77 771.68,226.75 771.68,225.95 771.395,225.665 771.03,225.665
  Bottom Layer w0.4: SIM1.G1@709.27,177.53 710.83,179.09 SIM1.4@711.695,179.09
  Bottom Layer w0.5: C21.1@708.49,218.568 709.648,218.568 710.02,218.94 710.02,221.59 709.36,222.25 709.36,223.96 ; 711.36,233.16 711.36,230.56 711.34,230.54 714.06,230.54 ; R55.2@713.007,235.58 713.137,235.71 716.17,235.71 ; 713.76,233.16 713.76,230.84 714.06,230.54 ; v1(716.8,223.98) 716.82,223.96 718.16,223.96 ; 719.02,235.79 719.36,235.45 719.36,233.16 719.36,230.38 ; 719.4,229.95 719.36,229.99 719.36,230.38 ; C19.1@720.636,219.077 722.119,219.077 C23.1@722.13,219.088 ; 721.36,223.96 721.36,222.85 722.07,222.14 v4(722.07,222.15) ; 721.62,235.53 721.76,235.39 721.76,233.16 721.76,230.38 ; 721.85,229.98 721.76,230.07 721.76,230.38 ; 722.46,230.23 722.56,230.33 722.56,230.38 ; 722.46,235.28 722.56,235.18 722.56,233.16 722.56,230.38 ; R121.2@723.63,220.588 R121.2@723.63,220.647 723.63,221.79 724.56,222.72 724.56,223.96 ; 724.36,235.25 724.96,234.65 724.96,233.16 724.96,230.75 724.59,230.38 724.11,230.38 722.56,230.38 ; 725.08,235.3 725.76,234.62 725.76,233.16 ; 726.96,223.96 726.96,222.3 727.878,221.382 R120.2@727.878,220.647 ; 728.16,233.16 728.16,231.54 730.67,229.03 v1(730.92,229.03) ; v1(744.03,237.07) 744.51,237.55 C13.1@745.488,237.55 ; C4.2@774.522,225.358 775.142,225.358 776.13,224.37 776.13,222.97 776.12,222.97 v1(776.11,222.98) ; R39.2@774.548,228.152 v1@775.298,228.902 ; 714.06,230.54 714.09,230.51 714.965,230.51 ; 714.06,230.54 714.935,230.54 714.965,230.51 ; 714.965,230.51 715.84,230.51 715.97,230.38 719.36,230.38 ; 719.36,230.38 721.76,230.38 ; 721.76,230.38 722.56,230.38
  other v1: 765.891,222.279 763.941,222.339 767.94,222.32 765.371,222.759 766.041,222.799 767.831,222.869 763.931,222.879 765.141,223.289 775.26,228.94
  other v2: 695.58,180.784 696.596,180.784 697.612,180.784 772.78,180.984 773.796,180.984 774.812,180.984 764.49,181.164 765.506,181.164 766.522,181.164 726.22,181.314 727.236,181.314 695.58,181.8 696.596,181.8 697.612,181.8 772.78,182 773.796,182 774.812,182 764.49,182.18 765.506,182.18 766.522,182.18 726.22,182.33 727.236,182.33 695.58,182.816 696.596,182.816 697.612,182.816 772.78,183.016 773.796,183.016 774.812,183.016 764.49,183.196 765.506,183.196 766.522,183.196 726.22,183.346 727.236,183.346 729.988,183.88 731.004,183.88 732.02,183.88 743.93,184.478 744.946,184.478 743.93,185.494 744.946,185.494 743.93,186.51 744.946,186.51 733.096,187.594 734.112,187.594 733.096,188.61 734.112,188.61 733.096,189.626 734.112,189.626 734.79,190.55 734.79,191.566 734.79,192.582 751.36,209.663 752.04,210.323 749.976,211.031 712.77,213.544 713.786,213.544 712.77,214.56 713.786,214.56 712.77,215.576 713.786,215.576 712.77,216.592 698.474,222.15 699.49,222.15 700.506,222.15 698.474,223.166 699.49,223.166 700.506,223.166 757.08,241.844 758.096,241.844 759.112,241.844 757.08,242.86 758.096,242.86 759.112,242.86 757.08,243.876 758.096,243.876 759.112,243.876
  other v3: 763.46,198.39 764.15,198.39 762.77,199.08 763.46,199.08 764.15,199.08 761.91,201.06 762.6,201.06 763.29,201.06 763.98,201.06 761.91,201.75 762.6,201.75 763.29,201.75 763.98,201.75 761.91,202.44 762.6,202.44
  other v4: 780.08,240.1 781.58,240.1 783.08,240.1
  other v5: 752.44,204.64 753.456,204.64 754.472,204.64
  other v6: 777.912,185.744 777.912,186.944 779.112,186.944
DIN1_N: Debug.2 U8.4 | length 16.6
  Top Layer w0.13: U8.4@780.537,186.594 780.657,186.474 782.854,186.474 784.28,185.048 v1@784.28,178.76 ; v1@784.28,178.96 784.41,178.83 v1(784.44,178.83) ; v1(785.59,180.645) 788.01,180.645 Debug.2@788.045,180.61
  Layer 1 w0.13: v1@784.28,178.79 784.28,180.13 784.955,180.805 785.43,180.805 v1(785.59,180.645) ; 784.28,178.99 v1(784.44,178.83)
DIN1_P: Debug.3 U8.3 | length 16.6
  Top Layer w0.13: U8.3@780.537,186.094 780.657,186.214 782.747,186.214 784.02,184.94 v1@784.02,178.76 ; v1(783.86,178.83) 783.89,178.83 v1@784.02,178.96 ; v1(785.59,181.225) 788.01,181.225 Debug.3@788.045,181.26
  Layer 1 w0.13: v1(783.86,178.83) 784.02,178.99 ; v1@784.02,178.79 784.02,180.238 784.847,181.065 785.43,181.065 v1(785.59,181.225)
DVI_+5V: F2.1 HDMI.18 R34.1 R35.1 | length 24.7
  Top Layer w0.28: v4(772.24,241.62) 772.65,241.21 785.75,241.21 786.59,240.37 HDMI.18@786.59,238.099 786.59,236.46 786.47,236.34 786.47,235.814 787.58,234.704 R35.1@787.58,234.217 R34.1@789.064,234.217
  Bottom Layer w0.28: F2.1@770.74,241.981 771.879,241.981 v4(772.24,241.62)
ETH1_LED_Act: CORE.191 LAN.12 | length 39.4
  Top Layer w0.13: CORE.191@721.811,225.38 721.811,226.571 721.99,226.75 v1(722.52,226.75)
  Layer 1 w0.13: v1(722.52,226.75) 722.569,226.799 722.569,228.611 727.938,233.98 734.158,233.98 736.47,236.292 736.47,240.14 737.81,241.48 748.73,241.48 LAN.12@750.014,242.764
ETH1_LED_SPEED: CORE.193 LAN.14 | length 29.5
  Top Layer w0.13: CORE.193@721.211,225.38 721.211,226.546 721.925,227.26 v1@722.169,227.26
  Layer 1 w0.13: v1@722.169,227.26 722.169,228.579 727.83,234.24 734.05,234.24 736.21,236.4 736.21,241.03 737.944,242.764 LAN.14@739.296,242.764
  other v1: 722.149,227.25
ETH1_MDI0_N: CORE.175 LAN.3 | length 35.6
  Top Layer w0.2: v1(726.601,226.88) 726.671,226.88 726.711,226.84 726.711,225.48 CORE.175@726.611,225.38
  Layer 1 w0.2: v1(726.601,226.88) 726.711,226.99 726.711,227.746 727.226,228.26 728.696,228.26 731.506,225.45 733.786,225.45 735.306,223.93 746.323,223.93 750.2,227.807 750.2,230.68 749.84,231.04 749.39,231.04 749.1,230.75 LAN.3@749.1,229.81 ; LAN.3@749.42,229.2 LAN.3@749.42,229.94
ETH1_MDI0_P: CORE.173 LAN.2 | length 35.6
  Top Layer w0.2: CORE.173@727.211,225.38 727.111,225.48 727.111,226.84 727.151,226.88 v1(727.221,226.88)
  Layer 1 w0.2: v1(727.221,226.88) 727.111,226.99 727.111,227.58 727.391,227.86 728.53,227.86 731.34,225.05 733.62,225.05 735.07,223.6 746.46,223.6 750.6,227.74 750.6,230.846 750.076,231.37 749.88,231.37 749.57,231.68 749.57,231.97 749.95,232.35 LAN.2@750.17,232.35 ; LAN.2@750.123,232.303 LAN.2@750.17,232.35 ; LAN.2@750.37,232.35 LAN.2@750.17,232.35 ; LAN.2@750.39,232.57 LAN.2@750.17,232.35
ETH1_MDI1_N: CORE.179 LAN.5 | length 35.5
  Top Layer w0.2: v1(725.401,227.35) 725.441,227.35 725.511,227.28 725.511,225.48 CORE.179@725.411,225.38
  Layer 1 w0.2: v1(725.401,227.35) 725.511,227.46 725.511,227.966 727.866,230.32 733.827,230.32 736.37,227.777 736.37,226.61 737.68,225.3 745.153,225.3 747.67,227.817 747.67,230.57 747.29,230.95 746.85,230.95 746.56,230.66 LAN.5@746.56,229.81 ; LAN.5@746.88,229.2 747.03,229.35 LAN.5@747.03,230
ETH1_MDI1_P: CORE.177 LAN.4 | length 35.5
  Top Layer w0.2: CORE.177@726.011,225.38 725.911,225.48 725.911,227.28 725.981,227.35 v1(726.021,227.35)
  Layer 1 w0.2: v1(726.021,227.35) 725.911,227.46 725.911,227.8 728.101,229.99 733.69,229.99 736.04,227.64 736.04,226.473 737.543,224.97 745.29,224.97 748.07,227.75 748.07,230.736 747.526,231.28 747.29,231.28 747,231.57 747,231.77 747.523,232.293 747.573,232.293 LAN.4@747.63,232.35 ; LAN.4@747.83,232.35 LAN.4@747.63,232.35 ; LAN.4@747.85,232.57 LAN.4@747.63,232.35
ETH1_MDI2_N: CORE.183 LAN.7 | length 35.5
  Top Layer w0.2: v1(724.201,226.89) 724.301,226.89 724.311,226.88 724.311,225.48 CORE.183@724.211,225.38
  Layer 1 w0.2: v1(724.201,226.89) 724.311,227 724.311,228.137 728.544,232.37 735.82,232.37 737.61,230.58 737.61,227.65 738.56,226.7 738.73,226.7 743.333,226.7 745.12,228.487 745.12,230.68 744.83,230.97 744.21,230.97 744.02,230.78 LAN.7@744.02,229.81 ; LAN.7@744.34,229.2 LAN.7@744.34,229.97
ETH1_MDI2_P: CORE.181 LAN.6 | length 35.6
  Top Layer w0.2: CORE.181@724.811,225.38 724.711,225.48 724.711,226.88 724.721,226.89 v1(724.821,226.89)
  Layer 1 w0.2: v1(724.821,226.89) 724.711,227 724.711,227.971 728.78,232.04 735.683,232.04 737.28,230.443 737.28,227.513 738.423,226.37 743.47,226.37 745.52,228.42 745.52,230.846 745.066,231.3 744.65,231.3 744.47,231.48 744.47,231.73 LAN.6@745.09,232.35 ; LAN.6@745.29,232.35 LAN.6@745.09,232.35 ; LAN.6@745.31,232.57 LAN.6@745.09,232.35
ETH1_MDI3_N: CORE.187 LAN.9 | length 35.5
  Top Layer w0.2: v1(723.001,227.21) 723.111,227.1 723.111,225.48 CORE.187@723.011,225.38
  Layer 1 w0.2: v1(723.001,227.21) 723.111,227.32 723.111,228.418 728.263,233.57 737.65,233.57 739.03,232.19 739.03,231.11 739.31,230.83 739.58,230.83 739.99,230.42 739.99,229.87 739.03,228.91 739.03,228.17 739.22,227.98 741.853,227.98 742.61,228.737 742.61,230.52 742.25,230.88 741.8,230.88 741.48,230.56 LAN.9@741.48,229.81 ; LAN.9@741.8,229.2 742.01,229.41 LAN.9@742.01,229.96
ETH1_MDI3_P: CORE.185 LAN.8 | length 35.5
  Top Layer w0.2: CORE.185@723.611,225.38 723.511,225.48 723.511,227.1 v1(723.621,227.21)
  Layer 1 w0.2: v1(723.621,227.21) 723.511,227.32 723.511,228.351 728.4,233.24 737.513,233.24 738.7,232.053 738.7,230.973 739.173,230.5 739.443,230.5 739.66,230.283 739.66,230.007 738.7,229.047 738.7,228.033 739.083,227.65 741.99,227.65 743.01,228.67 743.01,229.601 743.008,229.603 743.008,230.457 743.01,230.459 743.01,230.67 742.47,231.21 742.2,231.21 741.99,231.42 741.99,231.79 LAN.8@742.77,232.57
G0: Display.31 RN4.8 | length 26.8
  Layer 1 w0.13: v1@765.518,211.53 765.518,211.182 766.53,210.17 778.37,210.17 778.95,209.59 778.95,202.76 778.8,202.61 778.319,202.61 778.259,202.67 777.878,202.67 777.608,202.4 777.608,202.31 v1(777.448,202.31)
  Bottom Layer w0.13: v1(765.518,211.73) 765.518,212.225 RN4.8@765.802,212.509 ; v1(777.448,202.31) 777.859,202.72 778.28,202.72 778.879,203.319 Display.31@779.871,203.319
G1: Display.30 RN4.7 | length 25.3
  Layer 1 w0.13: v1@766.599,211.53 v1(766.729,211.53) ; v1@766.767,211.568 767.225,211.11 767.83,211.11 768.47,210.47 778.74,210.47 779.25,209.96 779.25,202.54 778.81,202.1 778.14,202.1 778.08,202.04 778.08,202.198 v1(778.068,202.21)
  Bottom Layer w0.13: v1@766.602,211.533 RN4.7@766.602,212.509 ; v1(778.068,202.21) 778.305,202.21 778.914,202.819 Display.30@779.871,202.819
G2: Display.29 RN4.6 | length 26.4
  Layer 1 w0.13: v1(767.399,211.53) 767.8,211.53 768.56,210.77 779.12,210.77 779.55,210.34 779.55,202.224 779.066,201.74 778,201.74 777.8,201.54 777.798,201.54 v1(777.698,201.64)
  Bottom Layer w0.13: v1@767.402,211.533 RN4.6@767.402,212.509 ; v1(777.698,201.64) 777.799,201.74 778.261,201.74 778.469,201.947 778.473,201.947 778.844,202.319 Display.29@779.871,202.319
G3: Display.28 RN4.5 | length 25.5
  Layer 1 w0.13: v1(768.2,211.75) 768.2,211.529 768.659,211.07 779.296,211.07 779.85,210.516 779.85,202.1 779.03,201.28 v1(778.23,201.28)
  Bottom Layer w0.13: v1@768.202,211.533 RN4.5@768.202,212.509 ; v1(778.23,201.28) 778.769,201.819 Display.28@779.871,201.819
G4: Display.27 RN3.8 | length 32.5
  Layer 1 w0.13: v1(769.236,211.53) 772.346,214.64 780.817,214.64 783.45,212.007 783.45,210.4 783.46,210.39 783.46,201.2 783.45,201.19 783.45,201.07 v1(783.618,201.07)
  Bottom Layer w0.13: v1@769.239,211.533 RN3.8@769.239,212.509 ; Display.27@779.871,201.319 781.471,201.319 781.671,201.119 783.569,201.119 v1(783.618,201.07)
G5: Display.26 RN3.7 | length 31.5
  Layer 1 w0.13: v1@770.036,211.53 772.886,214.38 780.653,214.38 783.15,211.883 783.15,200.51 783.15,200.44 783.18,200.47 v1(783.318,200.47)
  Bottom Layer w0.13: v1@770.039,211.533 RN3.7@770.039,212.509 ; Display.26@779.871,200.819 781.651,200.819 782,200.47 v1(783.318,200.47)
  other v1: 769.936,211.53
G6: Display.25 RN3.6 | length 30.5
  Layer 1 w0.13: v1(770.836,211.53) 773.426,214.12 780.488,214.12 782.85,211.758 782.85,199.82 782.959,199.82 v1(783.018,199.88)
  Bottom Layer w0.13: v1@770.839,211.533 RN3.6@770.839,212.509 ; Display.25@779.871,200.319 781.581,200.319 782.02,199.88 v1(783.018,199.88)
G7: Display.24 RN3.5 | length 29.3
  Layer 1 w0.13: v1@771.636,211.53 773.966,213.86 780.324,213.86 782.55,211.634 782.55,199.5 782.76,199.29 v1(782.72,199.29)
  Bottom Layer w0.13: v1@771.639,211.533 RN3.5@771.639,212.509 ; Display.24@779.871,199.819 781.421,199.819 781.95,199.29 v1(782.72,199.29)
  other v1: 771.536,211.53
GPIO0_18: CORE.163 PORT.19 R14.1 | length 78.7
  Top Layer w0.13: CORE.163@730.211,225.38 730.211,223.099 730.74,222.57 730.74,221.93 v1(730.75,221.92)
  Layer 1 w0.13: v1(730.75,221.92) 730.75,221.36 731.78,220.33 735.282,220.33 736.267,221.315 738.123,221.315 738.92,220.518 738.92,219.4 739.11,219.21 739.11,219.13 739.13,219.11 739.13,219.081 v1(739.169,219.12) ; v1(741.78,207.28) 741.78,190.653 741.76,190.633 741.759,190.631 743.03,189.36 743.03,187.44 743.01,187.42 743.01,182.43 745.6,179.84 v1(746.59,179.84)
  Layer 2 w0.13: v1(739.169,219.12) 741.76,216.528 741.78,216.508 v1(741.78,207.28)
  Bottom Layer w0.13: R14.1@735.22,201.657 740.643,207.08 740.843,207.28 v1(741.78,207.28) ; v1(746.59,179.84) 746.53,179.78 746.53,178.23 746.69,178.07 747.34,178.07 748.62,176.79 748.62,170.98 PORT.19@747.49,169.85
GPIO0_19: CORE.101 eMOD1.4 PORT.20 | length 73.5
  Top Layer w0.13: v1(745.21,222.56) 745.2,222.55 748.05,222.55 748.811,223.311 CORE.101@748.811,225.38
  Layer 1 w0.13: v1(745.09,209.09) 743.39,209.09 742.22,207.92 742.22,190.79 747.31,185.7 v1(747.31,180.37)
  Layer 2 w0.13: v1(745.09,209.09) 746.07,210.07 746.07,215.94 748.79,218.66 748.79,220.38 v1(748.42,220.75)
  Bottom Layer w0.13: v1(745.21,222.56) 745.27,222.62 eMOD1.4@745.27,224.16 745.27,225.5 745.69,225.92 746.58,225.92 748.42,224.08 v1(748.42,220.75) ; v1(747.31,180.37) 746.28,180.37 745.95,180.04 745.95,178.29 746.43,177.81 747.16,177.81 747.85,177.12 747.85,172.39 PORT.20@747.49,172.39
GPIO0_20: CORE.165 PORT.21 | length 70.9
  Top Layer w0.13: CORE.165@729.611,225.38 729.611,222.879 730.11,222.38 v1(730.11,221.96)
  Layer 1 w0.13: v1(730.11,221.96) 730.11,221.448 731.488,220.07 735.39,220.07 736.375,221.055 738.015,221.055 738.66,220.41 v1(738.66,218.8) ; v1(741.339,207.71) 741.339,190.441 742.75,189.03 742.75,182.22 745.63,179.34 v1(747.44,179.34)
  Layer 2 w0.13: v1(738.66,218.8) 741.339,216.121 v1(741.339,207.71)
  Bottom Layer w0.13: v1(747.44,179.34) 747.44,179.53 747.54,179.43 748.04,179.43 748.88,178.59 748.88,171 PORT.21@750.03,169.85
GPIO1_16: CORE.73 PORT.25 | length 80.7
  Top Layer w0.13: CORE.73@757.211,225.38 757.211,221.679 759.58,219.31 759.58,218.716 v1(759.57,218.706)
  Layer 1 w0.13: v1(753.07,178.58) 753.11,178.62 753.11,181.41 757.3,185.6 760.18,185.6 771.23,196.65 771.23,204.57 769.49,206.31 765.19,206.31 763.38,208.12 762.21,208.12 761.13,209.2 757.21,209.2 755.067,211.343 755.067,214.203 v1(759.57,218.706)
  Bottom Layer w0.13: v1(753.07,178.58) 753.07,174.66 753.91,173.82 753.91,170.91 754.97,169.85 PORT.25@755.11,169.85
GPIO1_17: CORE.95 PORT.26 | length 65
  Top Layer w0.13: v1(747.779,179.92) 747.843,179.855 750.505,179.855 v1(750.51,179.85) ; v1(749.41,220.2) 750.611,221.401 CORE.95@750.611,225.38
  Layer 1 w0.13: v1(745.07,208.33) 743.2,208.33 742.63,207.76 742.63,191.27 747.15,186.75 747.18,186.75 747.83,186.1 747.83,179.95 747.86,179.92 v1(747.779,179.92) ; v1(750.51,179.85) v1(753.65,176.71)
  Layer 2 w0.13: v1(745.07,208.33) 746.42,208.33 749.41,211.32 v1(749.41,220.2)
  Bottom Layer w0.13: v1(753.65,176.71) 755.11,175.25 PORT.26@755.11,172.39
GPIO1_18: CORE.81 PORT.27 | length 61.1
  Top Layer w0.13: CORE.81@754.811,225.38 754.811,221.869 755.7,220.98 755.7,220.21 755.73,220.21 v1(755.75,220.23)
  Bottom Layer w0.13: v1(755.75,220.23) 755.75,217.593 753.93,215.773 753.93,210.369 759.94,204.359 759.94,177.04 756.47,173.57 756.47,171.03 PORT.27@757.65,169.85
GPIO1_19: CORE.79 PORT.28 | length 57.9
  Top Layer w0.13: CORE.79@755.411,225.38 755.411,223.561 755.27,223.42 755.27,222.03 755.72,221.58 755.829,221.58 v1(755.768,221.52)
  Bottom Layer w0.13: v1(755.768,221.52) 755.768,221.242 756.178,220.832 756.178,217.654 754.19,215.665 754.19,210.477 760.2,204.467 760.2,175.798 757.65,173.248 PORT.28@757.65,172.39
GPIO1_20: CORE.77 PORT.29 | length 60.4
  Top Layer w0.13: CORE.77@756.011,225.38 756.011,223.391 755.77,223.15 755.77,222.13 756.45,221.45 756.45,221.39 v1@756.44,221.38
  Bottom Layer w0.13: v1(756.438,221.38) 756.438,217.546 754.45,215.558 754.45,210.585 760.46,204.575 760.46,175.69 758.97,174.2 758.97,171.05 760.17,169.85 PORT.29@760.19,169.85
GPIO1_21: CORE.75 PORT.30 | length 56.8
  Top Layer w0.13: CORE.75@756.611,225.38 756.611,221.819 756.94,221.49 756.94,220.33 v1@756.95,220.33 ; v1(756.928,220.33) v1@756.95,220.33
  Bottom Layer w0.13: v1(756.928,220.33) 756.928,217.668 754.71,215.45 754.71,210.692 760.72,204.682 760.72,172.92 PORT.30@760.19,172.39
GPIO1_22: CORE.83 PORT.31 | length 60.8
  Top Layer w0.13: CORE.83@754.211,225.38 754.211,221.639 754.91,220.94 754.92,220.94 v1(754.94,220.92) ; v1(759.15,178.18) 760.35,176.98 760.35,174.69 761.55,173.49 761.55,171.03 PORT.31@762.73,169.85
  Bottom Layer w0.13: v1(754.94,220.92) 755.28,220.58 755.28,217.491 753.67,215.881 753.67,210.262 759.68,204.252 759.68,178.71 v1(759.15,178.18)
GPIO1_23: CORE.85 PORT.32 | length 58.3
  Top Layer w0.13: CORE.85@753.611,225.38 753.628,225.363 753.628,221.442 754.81,220.26 v1(754.81,220.25) ; v1(759.01,179.2) 762.73,175.48 PORT.32@762.73,172.39
  Bottom Layer w0.13: v1(754.81,220.25) 754.81,217.388 753.41,215.988 753.41,210.154 759.42,204.144 759.42,179.61 v1(759.01,179.2)
GPIO3_17: CORE.36 Display.4 PORT.22 | length 71.3
  Top Layer w0.13: CORE.36@770.711,217.18 770.711,214.549 772.01,213.25 772.01,210.8 773.4,209.41 v1(773.4,205.82)
  Layer 1 w0.13: PORT.22@750.03,172.39 750.03,174.07 751.24,175.28 758.38,175.28 761.65,178.55 761.65,185 765.02,188.37 771.47,188.37 ; 772.055,188.955 771.47,188.37 ; v1(773.4,205.82) 773.4,190.3 771.47,188.37
  Bottom Layer w0.13: v1(772.93,189.86) 772.93,189.84 772.951,189.819 Display.4@779.871,189.819
GPIO3_18: CORE.38 Display.5 PORT.23 | length 71.8
  Top Layer w0.13: CORE.38@770.111,217.18 770.111,213.369 770.39,213.09 770.39,211.21 770.99,210.61 771.832,210.61 773.14,209.302 773.14,206.37 772.925,206.155 772.925,205.166 772.664,204.905 772.625,204.905 772.4,204.68 v1(772.388,204.68)
  Layer 1 w0.13: PORT.23@752.57,169.85 753.8,171.08 753.8,173.41 754.95,174.56 v1(756.29,174.56) ; v1(756.32,176.84) 756.37,176.84 758.29,178.76 759.58,178.76 760.8,179.98 760.8,185.45 764.7,189.35 770.17,189.35 v1(771.11,190.29) 772.288,191.468 772.288,199.302 771.56,200.03 771.56,202.34 772.1,202.88 772.1,204.391 v1(772.388,204.68)
  Bottom Layer w0.13: v1(756.29,174.56) 756.32,174.59 v1(756.32,176.84) ; v1(771.11,190.29) 771.139,190.319 Display.5@779.871,190.319
GPIO3_19: "SD CARD.9" CORE.117 R4.1 | length 52.5
  Top Layer w0.13: CORE.117@744.011,225.38 744.011,227.791 745.01,228.79 751.95,228.79 754.42,231.26 755.072,231.26 755.082,231.25 755.31,231.25 755.33,231.27 v1(755.36,231.27)
  Layer 2 w0.13: v1(755.36,231.27) 771.55,231.27 772.45,232.17 772.45,235.39 772.99,235.93 776.87,235.93 777.28,235.52 777.28,234.91 776.74,234.37 776.74,234.1 776.46,233.82 776.31,233.82 776.148,233.658 v1(776.148,233.04) ; v1@776.12,233.04 v1(776.148,233.04)
  Bottom Layer w0.13: R4.1@752.277,226.7 753.06,227.483 753.06,229.98 754.35,231.27 v1(755.36,231.27) ; 775.734,231.347 775.734,232.625 v1(776.148,233.04)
